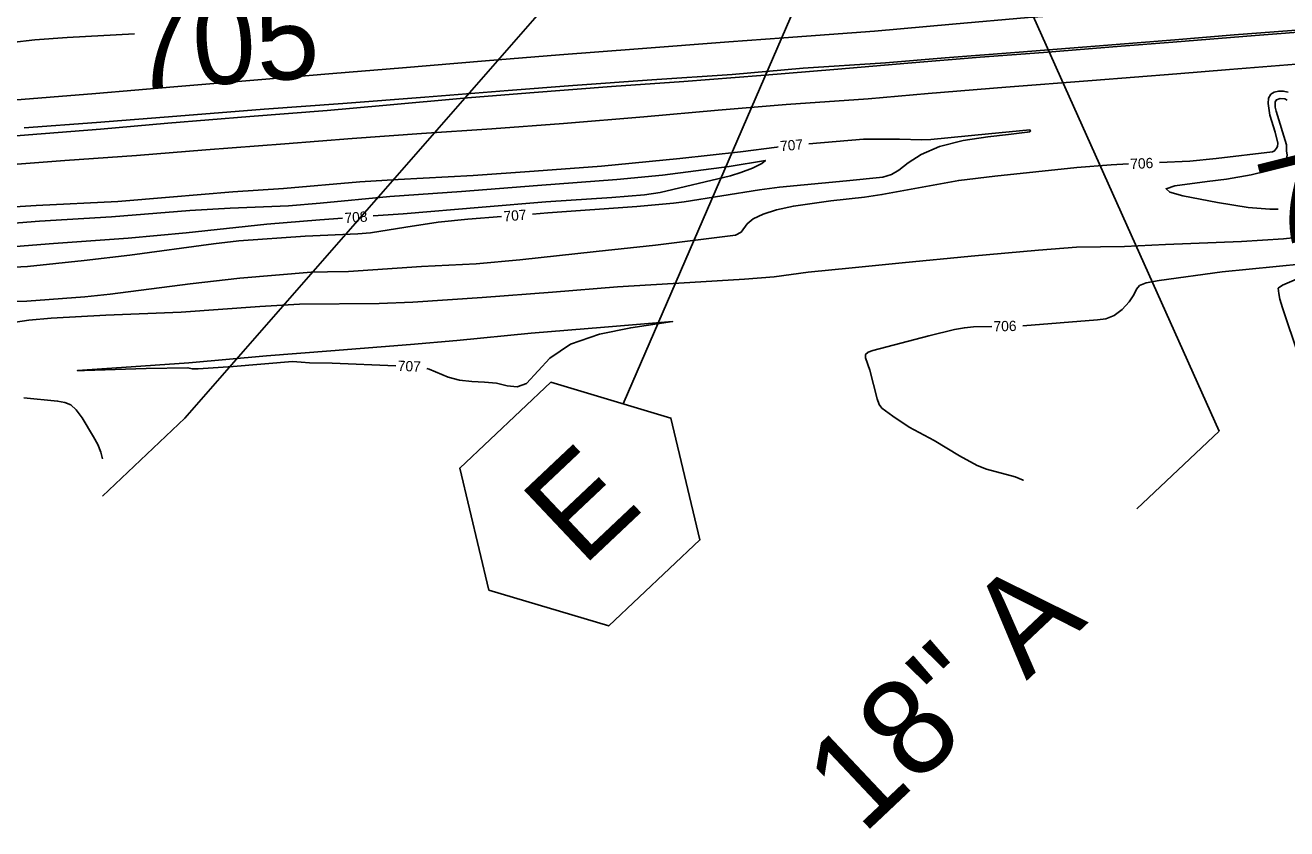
# Model space of a CAD drawing. Extents: x -291892836 to 2945206, y -477993085 to 1832792.
# Drawn here: x 1852246.4 to 1852737.2, y 543354.9 to 543667.6 of the extents above; entities that cross this region are included whole.
import ezdxf

# ---------------------------------------------------------------- set-up
doc = ezdxf.new("R2010")
doc.units = 0
for name, color, linetype in [('DT_X_Contour_Minor', 7, 'Continuous'), ('DT_X_Terrain_Ground_Line', 7, 'Continuous'), ('Level 19', 7, 'Continuous'), ('Level 40', 7, 'Continuous')]:
    doc.layers.add(name, color=color, linetype=linetype)

msp = doc.modelspace()

# ---------------------------------------------------------------- linework, layer by layer
at = {"layer": 'DT_X_Contour_Minor'}
for points in [[(1852740.93, 543678.48), (1852711.64, 543676.23), (1852685.12, 543674.22), (1852651.82, 543671.63), (1852636.62, 543670.58), (1852607.15, 543668.04), (1852576.86, 543665.34), (1852541.57, 543662.65), (1852520.13, 543661.11), (1852484.87, 543658.44), (1852454.26, 543656.05), (1852425.53, 543653.73), (1852393.18, 543651.03), (1852366.12, 543648.78), (1852336.94, 543646.35), (1852304.2, 543643.57), (1852273.93, 543641.07), (1852238.34, 543638.15)], [(1852026.8, 543640.23), (1852053.07, 543642.6), (1852081.91, 543646.06), (1852098.98, 543647.8), (1852127.62, 543650.01), (1852145.9, 543651.1), (1852167.39, 543652.28), (1852178.67, 543653.38), (1852207.07, 543656.79), (1852232.1, 543659.87), (1852250.09, 543661.92), (1852262.78, 543662.79), (1852288.97, 543664.27)], [(1852750.06, 543665.5), (1852724.87, 543663.54), (1852692.93, 543661), (1852672.73, 543659.4), (1852642.53, 543657.04), (1852617.93, 543655.16), (1852589.8, 543652.84), (1852562.6, 543650.5), (1852532.64, 543648.03), (1852502.67, 543645.7), (1852474.46, 543643.7), (1852442.73, 543641.33), (1852418.53, 543639.35), (1852385.51, 543636.34), (1852363.88, 543634.45), (1852333.73, 543632.08), (1852301.88, 543629.44), (1852275.69, 543627.21), (1852247.64, 543624.91), (1852213.99, 543622.21)], [(1852246.01, 543627.69), (1852274.15, 543629.75), (1852305.35, 543632.16), (1852339.4, 543634.91), (1852370, 543637.15), (1852401.86, 543639.61), (1852434.26, 543642.21), (1852459.4, 543644.09), (1852490.22, 543646.32), (1852521.41, 543648.45), (1852549.08, 543650.84), (1852581.03, 543652.98), (1852604.35, 543654.93), (1852633.05, 543657.16), (1852662.62, 543659.42), (1852693.72, 543661.95), (1852716.79, 543663.87), (1852744.41, 543666)], [(1852236.36, 543613.04), (1852261.85, 543614.97), (1852289.75, 543616.97), (1852316.62, 543619.06), (1852347.42, 543621.48), (1852373.65, 543623.5), (1852400.62, 543625.45), (1852427.99, 543627.33), (1852455.8, 543629.39), (1852487.1, 543632), (1852516.02, 543634.6), (1852542.46, 543636.77), (1852574.33, 543638.91), (1852597.69, 543640.97), (1852627.91, 543643.45), (1852661.53, 543646.05), (1852694.44, 543648.69), (1852714.95, 543650.35), (1852747.3, 543653.01)], [(1852687.68, 543614.15), (1852699.48, 543614.69), (1852709.72, 543615.68), (1852731.6, 543618.33), (1852732.48, 543618.75), (1852733.22, 543619.71), (1852733.62, 543620.41), (1852733.72, 543621.68), (1852732.68, 543625.93), (1852730.65, 543632.64), (1852729.94, 543637.19), (1852730.13, 543639.28), (1852730.98, 543640.71), (1852732.35, 543641.53), (1852734.05, 543641.92), (1852735.87, 543641.98), (1852737.76, 543641.55)], [(1852737.39, 543638.4), (1852736.45, 543638.96), (1852734.64, 543639.14), (1852733.15, 543638.55), (1852732.73, 543637.85), (1852732.75, 543635.73), (1852733.07, 543634.1), (1852737.11, 543621.1), (1852737.11, 543618.73), (1852737.42, 543617.05), (1852736.98, 543614.96), (1852734.62, 543612.82), (1852729.66, 543610.95), (1852723.41, 543609.44), (1852713.78, 543607.7), (1852706.2, 543606.79), (1852693.68, 543605.15), (1852690.26, 543604), (1852691.66, 543602.68), (1852696.71, 543601.27), (1852710.31, 543598.58), (1852722.25, 543596.68), (1852730.6, 543596.02), (1852733.85, 543596.07)], [(1852551.3, 543621.47), (1852572.5, 543623.24), (1852586.52, 543623.26), (1852595.22, 543622.94), (1852598.71, 543623.13), (1852621.14, 543625.35), (1852637.29, 543626.86), (1852637.52, 543626.42), (1852637.14, 543626.16), (1852636.22, 543625.93), (1852628.97, 543625.08), (1852620.95, 543624.17), (1852611.33, 543622.68), (1852602.15, 543620.41), (1852595.01, 543617.31), (1852589.88, 543613.99), (1852586.25, 543611.19), (1852583.47, 543609.48), (1852580.11, 543608.54), (1852565.86, 543607.06), (1852539.83, 543604.56), (1852532.06, 543603.52), (1852502.8, 543598.94), (1852498.6, 543598.31), (1852484.4, 543597.04), (1852449.77, 543594.59), (1852443.71, 543594.11)], [(1852138.98, 543590.09), (1852147.74, 543590.72), (1852168.9, 543592.05), (1852199.53, 543593.32), (1852209.65, 543594.06), (1852240.25, 543596.78), (1852250.61, 543597.42), (1852282.39, 543598.97), (1852302.5, 543600.68), (1852327.16, 543602.75), (1852346.89, 543604.1), (1852376.6, 543606.61), (1852391.5, 543607.51), (1852420.69, 543609.17), (1852444.43, 543610.84), (1852470.62, 543612.79), (1852501.13, 543615.73), (1852524.64, 543618.3), (1852538.83, 543620.21), (1852539.36, 543620.28)], [(1852221.01, 543588.95), (1852251.97, 543591.32), (1852280.01, 543593.08), (1852310.43, 543595.52), (1852326.11, 543596.35), (1852348.81, 543597.34), (1852361.14, 543598.37), (1852388.31, 543600.91), (1852416.19, 543602.94), (1852445.7, 543605.26), (1852476.57, 543607.51), (1852494.28, 543609.22), (1852520.3, 543612.58), (1852534.4, 543614.92), (1852533.01, 543613.79), (1852529.31, 543612), (1852524.86, 543610.23), (1852520.84, 543608.99), (1852493.4, 543602.56), (1852487.34, 543601.62), (1852474.61, 543600.55), (1852448.89, 543598.92), (1852424.12, 543596.86), (1852393.44, 543594.23), (1852381.83, 543593.38)], [(1852223.43, 543559.66), (1852247.03, 543560.24), (1852269.57, 543561.85), (1852279.42, 543562.97), (1852310.51, 543566.96), (1852329.83, 543569.11), (1852357.61, 543571.56), (1852364, 543571.62), (1852372.11, 543571.73), (1852400.63, 543573.67), (1852421.88, 543574.8), (1852438.87, 543576.28), (1852468.59, 543579.51), (1852491.56, 543581.98), (1852522.72, 543585.9), (1852524.91, 543587.1), (1852527.21, 543590.31), (1852529.63, 543592.2), (1852533.47, 543594.09), (1852538.73, 543595.82), (1852545.3, 543597.23), (1852559.79, 543599.24), (1852572.9, 543600.71), (1852579.71, 543601.72), (1852609.56, 543607.24), (1852623.63, 543608.89), (1852655.52, 543612.26), (1852668.84, 543613.28), (1852675.69, 543613.6)], [(1852369.87, 543592.49), (1852361.08, 543591.85), (1852340.42, 543590.25), (1852309.06, 543586.87), (1852286.49, 543584.79), (1852257.41, 543582.63), (1852229.64, 543580.49)], [(1852431.75, 543593.15), (1852418.57, 543592.1), (1852407.07, 543590.98), (1852394.46, 543589.03), (1852380.71, 543586.84), (1852375.86, 543586.4), (1852355.25, 543585.5), (1852329.56, 543583.66), (1852319.64, 543582.51), (1852287.11, 543578.09), (1852269.39, 543575.99), (1852247.29, 543573.68), (1852239.69, 543573.37)], [(1852740.73, 543584.95), (1852735.89, 543584.44), (1852719.55, 543583.5), (1852690.05, 543582.28), (1852674.03, 543581.53), (1852655.42, 543581.27), (1852640.56, 543580.08), (1852614.42, 543577.79), (1852587.53, 543575.14), (1852568.07, 543573.25), (1852550.97, 543571.57), (1852537.82, 543569.69), (1852526.19, 543568.72), (1852504.91, 543567.48), (1852476.79, 543565.82), (1852451.51, 543563.72), (1852424.15, 543561.62), (1852397.17, 543559.79), (1852384.04, 543559.35), (1852353.17, 543559), (1852337.67, 543558.11), (1852307.08, 543555.99), (1852277.72, 543554.73), (1852256.44, 543553.56), (1852247.86, 543552.77), (1852239.05, 543551.58)], [(1852634.47, 543550.67), (1852634.5, 543550.67), (1852663.6, 543552.97), (1852666.82, 543553.4), (1852670.01, 543554.65), (1852673.12, 543557.01), (1852675.83, 543559.95), (1852677.74, 543562.75), (1852678.76, 543564.84), (1852679.93, 543566.3), (1852682.57, 543567.37), (1852687.5, 543568.26), (1852712.09, 543571.64), (1852743.63, 543574.8)], [(1852740.99, 543568.72), (1852735.5, 543566.4), (1852733.92, 543565.27), (1852734.11, 543563.2), (1852734.57, 543560.97), (1852735.53, 543557.64), (1852741.78, 543539.02)], [(1852402.59, 543533.97), (1852403.59, 543533.71), (1852410.92, 543530.67), (1852415.31, 543529.42), (1852420.12, 543528.9), (1852425.05, 543528.72), (1852429.73, 543528.29), (1852433.93, 543527.31), (1852437.74, 543526.85), (1852441.39, 543528.24), (1852450.53, 543537.99), (1852458.5, 543543.46), (1852469.76, 543547.39), (1852481.97, 543549.85), (1852498.26, 543552.3), (1852471.77, 543550.17), (1852443.22, 543547.74), (1852414.37, 543544.96), (1852396.28, 543543.38), (1852365.29, 543540.94), (1852340.24, 543538.89), (1852310.06, 543536.29), (1852283.8, 543534.47), (1852266.68, 543533.19), (1852269.45, 543533.18), (1852293.46, 543534.02), (1852309.67, 543534.29), (1852311.39, 543533.91), (1852313.74, 543533.85), (1852327.24, 543534.85), (1852350.33, 543536.73), (1852353.73, 543536.49), (1852357.03, 543536.18), (1852365.78, 543536.09), (1852390.63, 543535.12)], [(1852634.8, 543490.53), (1852634.62, 543490.63), (1852631.52, 543491.85), (1852620.35, 543494.81), (1852616.71, 543496.3), (1852609.88, 543500.09), (1852600.06, 543506.03), (1852590.36, 543511.14), (1852583.92, 543515.43), (1852579.73, 543518.64), (1852578.65, 543520.05), (1852577.82, 543522.24), (1852575.01, 543533.42), (1852573.28, 543538.16), (1852573.32, 543539.47), (1852574.37, 543540.39), (1852576.18, 543541.07), (1852598, 543546.71), (1852607.97, 543549.18), (1852611.82, 543549.9), (1852615.33, 543550.26), (1852622.48, 543550.41)], [(1852245.89, 543522.55), (1852259, 543521.32), (1852261.87, 543520.8), (1852264.1, 543519.82), (1852266.19, 543517.91), (1852268.5, 543514.82), (1852273, 543507.44), (1852274.64, 543504.41), (1852275.84, 543501.49), (1852276.51, 543498.82)]]:
    msp.add_lwpolyline(points, dxfattribs=at)
at = {"layer": 'Level 40'}
for p, q in [((1852308.53, 543514.64), (1852577.68, 543822.73)), ((1852710.96, 543509.66), (1852579.71, 543802.42)), ((1852479.07, 543520.28), (1852580.11, 543753.54)), ((1852276.47, 543484.37), (1852308.53, 543514.64)), ((1852678.89, 543479.39), (1852710.96, 543509.66))]:
    msp.add_line(p, q, dxfattribs=at)
msp.add_lwpolyline([(1852426.72, 543447.81), (1852415.47, 543495.24), (1852450.92, 543528.7), (1852497.62, 543514.73), (1852508.88, 543467.3), (1852473.42, 543433.84)], close=True, dxfattribs=at)

# ---------------------------------------------------------------- texts
at = {"layer": 'DT_X_Terrain_Ground_Line'}
for rotation, p in [(4.0279, (1852288.12, 543642.25)), (14.1005, (1852731.66, 543580.79))]:
    msp.add_text('705', height=33, rotation=rotation, dxfattribs=at).set_placement(p)
at = {"layer": 'Level 19'}
for s, rotation, p in [('707', 4.767, (1852540.25, 543618.54)), ('706', 2.6241, (1852676.43, 543611.63)), ('708', 4.2112, (1852370.77, 543590.56)), ('707', 4.5722, (1852432.65, 543591.22)), ('706', 1.2319, (1852623.17, 543548.43)), ('707', 357.7663, (1852391.29, 543533.1))]:
    msp.add_text(s, height=4, rotation=rotation, dxfattribs=at).set_placement(p)
at = {"layer": 'Level 40'}
for s, p in [('E', (1852463.23, 543456.49)), ('18" A', (1852572.28, 543352.29))]:
    msp.add_text(s, height=37.5, rotation=43.3446, dxfattribs=at).set_placement(p)

doc.saveas('drawing.dxf')
